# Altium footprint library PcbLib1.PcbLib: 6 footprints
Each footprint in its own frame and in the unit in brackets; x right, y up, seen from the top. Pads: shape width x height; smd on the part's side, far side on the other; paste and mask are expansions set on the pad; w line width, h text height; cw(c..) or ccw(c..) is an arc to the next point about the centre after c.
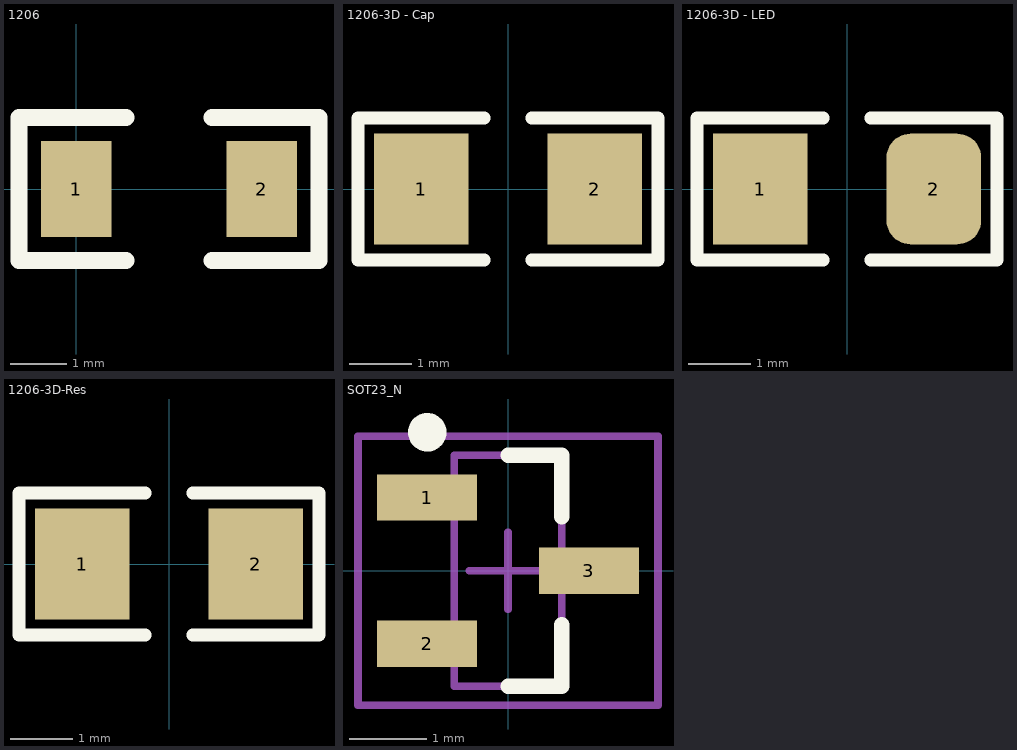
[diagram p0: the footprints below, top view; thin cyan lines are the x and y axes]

## 1206 [mm]
pads (2):
  rect 1.25x1.7 smd: 1(0,0) 2(3.3,0)
Top Overlay:
  lines w0.305: 0.889,-1.27 -1.016,-1.27 -1.016,1.27 0.889,1.27 ; 2.413,-1.27 4.318,-1.27 4.318,1.27 2.413,1.27

## 1206-3D - Cap [mil]
pads (2):
  rect 60x70 smd: 1(-55,0) 2(55,0)
Top Overlay:
  lines w8: -15,-45 -95,-45 -95,45 -15,45 ; 15,-45 95,-45 95,45 15,45
3D body "SW3dPS-1206 SMD Capacitor.STEP": height 39.45, standoff 0, extent -62.99,-30 62.99,33

## 1206-3D - LED [mil]
pads (2):
  rect 60x70 smd: 1(-55,0)
  rrect50% 60x70 smd: 2(55,0)
Top Overlay:
  lines w8: -15,-45 -95,-45 -95,45 -15,45 ; 15,-45 95,-45 95,45 15,45
3D body "User Library-LED 1206 RED.STEP": height 43.31, standoff 0, extent -61.99,-31.49 63.99,31.5

## 1206-3D-Res [mil]
pads (2):
  rect 60x70 smd: 1(-55,0) 2(55,0)
Top Overlay:
  lines w8: -15,-45 -95,-45 -95,45 -15,45 ; 15,-45 95,-45 95,45 15,45
3D body "SW3dPS-1206 SMD Resistor.STEP": height 39.45, standoff 0, extent -62.99,-31.5 62.99,31.5

## PCBComponent_1 [mil]

## SOT23_N [mm] "SOT23, 3-Leads, Body 2.9x1.3mm, Pitch 0.95mm, Lead Span 2.3mm, IPC Medium Density"
height 1.1
pads (3):
  rect 1.3x0.6 smd: 1(-1.05,0.95) 2(-1.05,-0.95) 3(1.05,0)
Top Overlay:
  circle w0.25: c-1.05,1.8 r0.125
  lines w0.2: 0,-1.5 0.7,-1.5 0.7,-0.7 ; 0,1.5 0.7,1.5 0.7,0.7
Mechanical 13:
  lines w0.1: -0.7,-1.5 -0.7,1.5 0.7,1.5 0.7,-1.5 -0.7,-1.5
Mechanical 15:
  lines w0.1: -0.5,0 0.5,0 ; 0,-0.5 0,0.5 ; -1.95,-1.75 -1.95,1.75 1.95,1.75 1.95,-1.75 -1.95,-1.75
3D body: height 1.1, standoff 0, extent -0.7,-1.5 0.7,1.5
